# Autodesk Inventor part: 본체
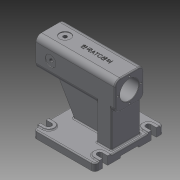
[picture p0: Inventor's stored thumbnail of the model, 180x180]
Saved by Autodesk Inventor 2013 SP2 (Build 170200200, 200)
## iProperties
Created: 2024-07
Part Number: 본체
Material: Generic
Document SubType Name: Modeling
Designer: 601
Density: 1 g/cm^3
Author: 601
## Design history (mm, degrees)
sketch "스케치1"
  geometry: L1 (-40, -40)-(40, -40); L2 (40, -40)-(40, 40); L3 (40, 40)-(-40, 40); L4 (-40, 40)-(-40, -40); L5 (-40, -40)-(40, 40); L6 (40, -40)-(-40, 40); 1 further point
  constraints: 12 end point, 2 midpoint, 2 parallel, 1 horizontal, 1 perpendicular
  dimensions: "d0" = 80 distance of L2.end L3.end; "d2" = 80 distance of L1.end L2.end
extrude "돌출1" new body sketch "스케치1" distance "d3" = 217; taper "d4" = 0 deg
node "작업 평면1"
sketch "스케치2"
  geometry: L1 (217, 40)-(217, -40) reference; L2 (47, 95)-(217, 95); L3 (217, 95)-(217, -95); L4 (217, -95)-(47, -95); L5 (47, -95)-(47, 95); 2 further points
  constraints: 8 end point, 2 parallel, 1 horizontal, 1 horizontal alignment, 1 midpoint, 1 perpendicular
  dimensions: "d6" = 170 distance of L2.start L2.end; "d8" = 190 distance of L2.end L3.end; "d9" = 0 distance between parallel lines of L1 L3
extrude "돌출2" join sketch "스케치2" distance "d10" = 20; taper "d11" = 0 deg
sketch "스케치3"
  geometry: L1 (47, 95)-(47, -95) reference; L2 (217, -95)-(217, 95) reference; L3 (79, 15)-(207, 15); L4 (207, 15)-(207, -15); L5 (207, -15)-(79, -15); L6 (79, -15)-(79, 15); L7 (167, 40)-(207, 40); L8 (207, 40)-(207, -40); L9 (207, -40)-(167, -40); L10 (167, -40)-(167, 40); 3 further points
  constraints: 16 end point, 4 parallel, 2 horizontal, 2 horizontal alignment, 2 midpoint, 2 perpendicular
  dimensions: "d12" = 80 distance of L7.end L8.end; "d14" = 30 distance of L5.end L3.start; "d15" = 40 distance of L8.end L9.end; "d16" = 10 distance between parallel lines of L2 L4; "d17" = 10 distance between parallel lines of L2 L8; "d18" = 32 distance between parallel lines of L1 L6
extrude "돌출3" join sketch "스케치3" stored distance "d19" = 20; taper "d20" = 0 deg
feature "면 기울기1" dims angle "d21" = -30 deg
sketch "스케치4"
  geometry: C1 r 20.5 at (0, 0); 1 further point
  constraints: 1 centre point, 1 coincident
  dimensions: "d22" = 41 diameter of C1
extrude "돌출4" cut sketch "스케치4" distance "d24" = 5; taper "d25" = 0 deg
sketch "스케치5"
  geometry: C1 r 26 at (0, 0); 1 further point
  constraints: 1 centre point, 1 coincident
  dimensions: "d26" = 52 diameter of C1
extrude "돌출5" cut sketch "스케치5" distance "d28" = 212; taper "d29" = 0 deg
sketch "스케치6"
  geometry: L1 (207, 40)-(207, -40) reference; L2 (207, -40)-(167, -40) reference; L3 (167, -40)-(167, -15) reference; L4 (167, -15)-(79, -15) reference; L5 (79, -15)-(79, 15) reference; L6 (79, 15)-(167, 15) reference; L7 (167, 15)-(167, 40) reference; L8 (167, 40)-(207, 40) reference; L9 (217, 95)-(47, 95) reference; L10 (47, 95)-(47, -95) reference; L11 (47, -95)-(217, -95) reference; L12 (217, -95)-(217, 95) reference; L13 (47, 0)-(217, 0); L14 (132, 95)-(132, -95); L15 (77, -67)-(187, -67); L16 (202, -52)-(202, 52); L17 (187, 67)-(62, 67); L18 (62, 52)-(62, -52); L19 (72.836, -56.628)-(202, 67); L20 (202, -67)-(72.836, 56.628); L21 (202, 82)-(217, 82); L22 (202, 52)-(217, 52); L23 (202, -52)-(217, -52); L24 (202, -82)-(217, -82); L25 (62, 52)-(47, 52); L26 (62, 82)-(47, 82); L27 (62, -82)-(47, -82); L28 (62, -52)-(47, -52); A1 r 15 centre (202, 67) between (202, 82) and (202, 52); A2 r 15 centre (202, -67) between (202, -52) and (202, -82); A3 r 15 centre (62, -67) between (62, -82) and (62, -52); A4 r 15 centre (62, 67) between (62, 52) and (62, 82); 2 further points
  constraints: 32 end point, 13 point on circle, 10 point on line, 9 parallel, 8 tangent, 5 midpoint, 4 centre point, 3 coincident, 2 perpendicular, 1 horizontal
  dimensions: "d30" = 134 distance of L20.start L19.end; "d32" = 140 distance of L19.end L17.end; "d33" = 30 diameter of A1; "d34" = 30 diameter of A2; "d35" = 30 diameter of A3; "d36" = 30 diameter of A4
extrude "돌출6" join sketch "스케치6" distance "d37" = 3; taper "d38" = 0 deg
sketch "스케치7"
  geometry: L1 (-217, 95)-(-217, -95) reference; L2 (-47, -95)-(-47, 95) reference; L3 (-47, 82)-(-62, 82) reference; L4 (-62, 52)-(-47, 52) reference; L5 (-202, 82)-(-217, 82) reference; L6 (-217, 52)-(-202, 52) reference; L7 (-217, -82)-(-202, -82) reference; L8 (-202, -52)-(-217, -52) reference; L9 (-47, -52)-(-62, -52) reference; L10 (-62, -82)-(-47, -82) reference; L11 (-47, 60)-(-62, 60); L12 (-62, 74)-(-47, 74); L13 (-217, 74)-(-202, 74); L14 (-202, 60)-(-217, 60); L15 (-217, -60)-(-202, -60); L16 (-202, -74)-(-217, -74); L17 (-47, -74.687)-(-62, -74.687); L18 (-62, -59.313)-(-47, -59.313); L19 (-202, -60)-(-202, -74); L20 (-202, 60)-(-202, 74); L21 (-217, -60)-(-217, -74); L22 (-47, -74.687)-(-47, -59.313); L23 (-47, 60)-(-47, 74); L24 (-217, 60)-(-217, 74); A1 r 15 centre (-62, 67) between (-62, 82) and (-62, 52) reference; A2 r 15 centre (-202, 67) between (-202, 52) and (-202, 82) reference; A3 r 15 centre (-202, -67) between (-202, -82) and (-202, -52) reference; A4 r 15 centre (-62, -67) between (-62, -52) and (-62, -82) reference; A5 r 7 centre (-62, 67) between (-62, 74) and (-62, 60); A6 r 7 centre (-202, 67) between (-202, 60) and (-202, 74); A7 r 7 centre (-202, -67) between (-202, -74) and (-202, -60); A8 r 7.687 centre (-62, -67) between (-62, -59.313) and (-62, -74.687); 1 further point
  constraints: 28 end point, 9 point on circle, 4 centre point, 4 collinear, 1 parallel, 1 perpendicular, 8 other
  dimensions: "d39" = 7 radius of A5; "d41" = 7 radius of A6; "d42" = 7 radius of A7; "d43" = 7.68661 radius of A8
extrude "돌출7" cut sketch "스케치7" distance "d44" = 23; taper "d45" = 0 deg
sketch "스케치8"
  geometry: L1 (217, 80)-(217, 0) reference; L2 (0, 80)-(0, 0) reference; L3 (217, 40)-(40, 40); C1 r 15 at (40, 40); 1 further point
  constraints: 2 end point, 1 centre point, 1 coincident, 1 midpoint, 1 perpendicular
  dimensions: "d46" = 177 distance of L3.start L3.end; "d48" = 30 diameter of C1
extrude "돌출8" cut sketch "스케치8" distance "d49" = 2; taper "d50" = 0 deg
sketch "스케치9"
  geometry: L1 (217, 80)-(217, 0) reference; L2 (0, 0)-(167, 0) reference; L3 (217, 40)-(40, 40); C1 r 15 at (40, 40); 1 further point
  constraints: 2 end point, 1 centre point, 1 coincident, 1 midpoint, 1 parallel
  dimensions: "d60" = 177 distance of L3.start L3.end; "d62" = 30 diameter of C1
extrude "돌출9" cut sketch "스케치9" distance "d63" = 2; taper "d64" = 0 deg
hole "구멍2" diameter "d67" = 10.106; stored, may be unused: countersink angle "d71" = 90 deg, drill point angle "d73" = 118 deg; dims "d65" = 10, "d66" = 10, "d68" = 20, "d69" = 30, "d70" = 2, "d72" = 20
hole "구멍3" diameter "d76" = 10.106; stored, may be unused: countersink angle "d80" = 90 deg, drill point angle "d82" = 118 deg; dims "d74" = 10, "d75" = 10, "d77" = 30, "d78" = 30, "d79" = 2, "d81" = 30
sketch "스케치10"
  geometry: L1 (-40, -40)-(40, -40) reference; L2 (0, 0)-(-32, 0); C1 r 26 at (0, 0) reference
  constraints: 2 end point, 1 parallel
  dimensions: "d83" = 32 distance of L2.start L2.end
hole "구멍4" sketch "스케치10" at (-32, 0) diameter "d84" = 4.917; stored, may be unused: countersink angle "d88" = 90 deg, drill point angle "d90" = 118 deg; dims "d85" = 12, "d86" = 30, "d87" = 2, "d89" = 14
node "작업 평면2"
sketch "스케치11"
  geometry: L1 (217, 40)-(217, -40) reference; L2 (0, 40)-(0, -40) reference; 3 further points
  constraints: 1 horizontal alignment, 1 midpoint, 1 other
  dimensions: "d95" = 90 distance from line of point (127, 0) L1
feature "엠보싱1" sketch "스케치11" dims "d96" = 0.5, "d97" = 0
fillet "모깎기1" dims "d98" = 15
fillet "모깎기2" dims "d99" = 15
fillet "모깎기3" dims "d100" = 10
sketch "스케치12"
  geometry: L1 (-47, -59.313)-(-47, 60) reference; L2 (-132.58, 0.17)-(-131.412, 0.173); L3 (-132, 0.172)-(-132, 0); L4 (-217, -25)-(-47, -25); L5 (-47, -25)-(-47, 25); L6 (-47, 25)-(-217, 25); L7 (-217, 25)-(-217, -25); L8 (-217, -25)-(-47, 25); L9 (-47, -25)-(-217, 25); 1 further point
  constraints: 16 end point, 4 point on line, 2 midpoint, 2 parallel, 1 horizontal, 1 perpendicular
  dimensions: "d101" = 50 distance of L6.end L4.start
extrude "돌출10" cut sketch "스케치12" distance "d103" = 5; taper "d104" = 0 deg
chamfer "모따기1" distance "d105" = 1; stored, may be unused: second distance "d106" = 2, angle "d107" = 45 deg
fillet "모깎기4" dims "d108" = 3
fillet "모깎기5" dims "d109" = 3
fillet "모깎기6" dims "d110" = 3
fillet "모깎기7" dims "d111" = 3
fillet "모깎기8" dims "d112" = 3
fillet "모깎기9" dims "d113" = 1
fillet "모깎기10" dims "d114" = 3
node "솔리드1"
mirror "대칭1"
pattern_circular "원형 패턴1" dims angle "d92" = 360 deg
node "투영된 루프1"
